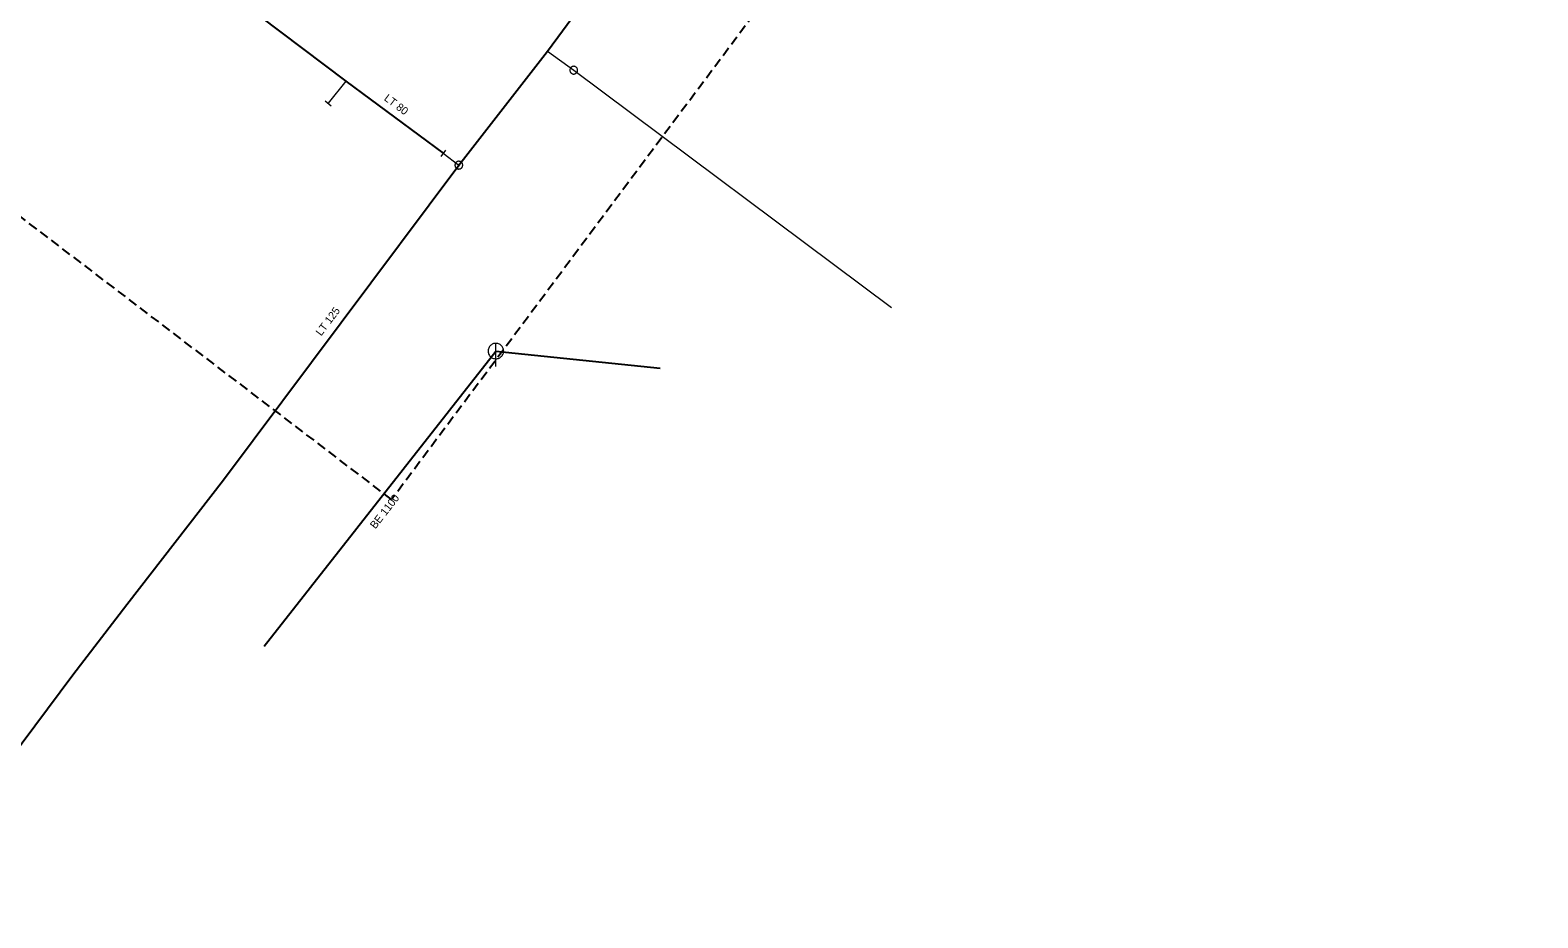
# Model space of a CAD drawing. Extents: x -791337 to -790755, y -988454 to -987923.
# Drawn here: x -790949.7 to -790755.1, y -988454.4 to -988339.8 of the extents above; entities that cross this region are included whole.
import ezdxf

# ---------------------------------------------------------------- set-up
doc = ezdxf.new("R2010")
doc.units = 0
doc.header["$LTSCALE"] = 0.4
doc.linetypes.add('MEDIUM_DASHED', pattern=[4.5, 3, -1.5])
for name, color, linetype, lineweight in [('1', 7, 'Continuous', 13), ('13', 7, 'Continuous', 13), ('14', 7, 'Continuous', 25), ('17', 7, 'Continuous', 25), ('22', 7, 'Continuous', 13), ('23', 7, 'Continuous', 13), ('34', 7, 'Continuous', 13), ('47', 7, 'Continuous', 13), ('63', 7, 'MEDIUM_DASHED', 25)]:
    doc.layers.add(name, color=color, linetype=linetype, lineweight=lineweight)

msp = doc.modelspace()

# ---------------------------------------------------------------- linework, layer by layer
at = {"layer": '13'}
for p, q in [((-790882.949, -988342.528), (-790879.522, -988345.001)), ((-790879.522, -988345.001), (-790838.539, -988375.636)), ((-790908.984, -988346.43), (-790911.247, -988349.284))]:
    msp.add_line(p, q, dxfattribs=at)
at = {"layer": '14', "lineweight": 13}
msp.add_line((-790896.409, -988355.739), (-790894.383, -988357.266), dxfattribs=at)
at = {"layer": '14'}
for p, q in [((-790919.509, -988419.376), (-790889.6, -988381.27)), ((-790889.6, -988381.27), (-790868.41, -988383.46))]:
    msp.add_line(p, q, dxfattribs=at)
at = {"layer": '17'}
for points in [[(-790942.565, -988321.078), (-790942.351, -988321.278), (-790925.727, -988333.706), (-790908.984, -988346.43), (-790896.409, -988355.739)], [(-790894.383, -988357.266), (-790882.949, -988342.528), (-790868.671, -988323.153)], [(-790967.649, -988454.445), (-790967.006, -988453.631), (-790944.219, -988423.054), (-790937.217, -988413.973), (-790924.743, -988397.888), (-790894.383, -988357.266)]]:
    msp.add_lwpolyline(points, dxfattribs=at)
at = {"layer": '22'}
msp.add_line((-790889.6, -988383.27), (-790889.599, -988380.27), dxfattribs=at)
msp.add_lwpolyline([(-790888.6, -988381.27), (-790888.605, -988381.161), (-790888.623, -988381.053), (-790888.653, -988380.947), (-790888.693, -988380.846), (-790888.745, -988380.749), (-790888.807, -988380.659), (-790888.879, -988380.576), (-790888.959, -988380.502), (-790889.047, -988380.436), (-790889.141, -988380.381), (-790889.241, -988380.336), (-790889.346, -988380.303), (-790889.453, -988380.281), (-790889.562, -988380.271), (-790889.672, -988380.273), (-790889.78, -988380.287), (-790889.887, -988380.312), (-790889.99, -988380.349), (-790890.088, -988380.398), (-790890.18, -988380.456), (-790890.266, -988380.525), (-790890.343, -988380.602), (-790890.412, -988380.688), (-790890.471, -988380.78), (-790890.519, -988380.878), (-790890.556, -988380.981), (-790890.582, -988381.088), (-790890.596, -988381.196), (-790890.599, -988381.306), (-790890.589, -988381.415), (-790890.568, -988381.522), (-790890.534, -988381.626), (-790890.49, -988381.726), (-790890.435, -988381.821), (-790890.369, -988381.909), (-790890.295, -988381.989), (-790890.212, -988382.061), (-790890.122, -988382.123), (-790890.026, -988382.175), (-790889.924, -988382.216), (-790889.819, -988382.246), (-790889.711, -988382.264), (-790889.601, -988382.27), (-790889.492, -988382.264), (-790889.384, -988382.246), (-790889.279, -988382.217), (-790889.177, -988382.176), (-790889.08, -988382.124), (-790888.99, -988382.062), (-790888.907, -988381.991), (-790888.832, -988381.911), (-790888.767, -988381.823), (-790888.711, -988381.729), (-790888.667, -988381.629), (-790888.633, -988381.525), (-790888.611, -988381.417), (-790888.601, -988381.308)], close=True, dxfattribs=at)
at = {"layer": '23'}
for points in [[(-790879.15, -988345.3), (-790879.121, -988345.256), (-790879.097, -988345.209), (-790879.079, -988345.161), (-790879.065, -988345.11), (-790879.057, -988345.059), (-790879.055, -988345.006), (-790879.057, -988344.954), (-790879.065, -988344.903), (-790879.078, -988344.852), (-790879.097, -988344.803), (-790879.12, -988344.756), (-790879.149, -988344.711), (-790879.182, -988344.671), (-790879.218, -988344.635), (-790879.258, -988344.601), (-790879.304, -988344.572), (-790879.349, -988344.549), (-790879.399, -988344.53), (-790879.448, -988344.516), (-790879.5, -988344.507), (-790879.553, -988344.505), (-790879.605, -988344.508), (-790879.658, -988344.516), (-790879.708, -988344.528), (-790879.756, -988344.547), (-790879.803, -988344.572), (-790879.846, -988344.6), (-790879.887, -988344.633), (-790879.924, -988344.67), (-790879.957, -988344.71), (-790879.986, -988344.754), (-790880.01, -988344.801), (-790880.029, -988344.85), (-790880.043, -988344.9), (-790880.05, -988344.951), (-790880.053, -988345.003), (-790880.051, -988345.056), (-790880.043, -988345.108), (-790880.029, -988345.159)], [(-790879.399, -988344.53), (-790879.448, -988344.516), (-790879.5, -988344.507), (-790879.553, -988344.505), (-790879.605, -988344.508), (-790879.658, -988344.516), (-790879.708, -988344.528), (-790879.756, -988344.547), (-790879.803, -988344.572), (-790879.846, -988344.6), (-790879.887, -988344.633), (-790879.924, -988344.67), (-790879.957, -988344.71), (-790879.986, -988344.754), (-790880.01, -988344.801), (-790880.029, -988344.85), (-790880.043, -988344.9), (-790880.05, -988344.951), (-790880.053, -988345.003), (-790880.051, -988345.056), (-790880.043, -988345.108), (-790880.029, -988345.159), (-790880.011, -988345.207), (-790879.987, -988345.254), (-790879.96, -988345.298), (-790879.925, -988345.339), (-790879.889, -988345.375), (-790879.849, -988345.408), (-790879.805, -988345.436), (-790879.758, -988345.461), (-790879.709, -988345.48), (-790879.659, -988345.493), (-790879.607, -988345.502), (-790879.555, -988345.505), (-790879.502, -988345.501), (-790879.451, -988345.494), (-790879.401, -988345.481), (-790879.351, -988345.462), (-790879.304, -988345.438), (-790879.261, -988345.41)], [(-790880.029, -988345.159), (-790880.011, -988345.207), (-790879.987, -988345.254), (-790879.96, -988345.298), (-790879.925, -988345.339), (-790879.889, -988345.375), (-790879.849, -988345.408), (-790879.805, -988345.436), (-790879.758, -988345.461), (-790879.709, -988345.48), (-790879.659, -988345.493), (-790879.607, -988345.502), (-790879.555, -988345.505), (-790879.502, -988345.501), (-790879.451, -988345.494), (-790879.401, -988345.481), (-790879.351, -988345.462), (-790879.304, -988345.438), (-790879.261, -988345.41), (-790879.22, -988345.376), (-790879.183, -988345.34), (-790879.15, -988345.3), (-790879.121, -988345.256), (-790879.097, -988345.209), (-790879.079, -988345.161), (-790879.065, -988345.11), (-790879.057, -988345.059), (-790879.055, -988345.006), (-790879.057, -988344.954), (-790879.065, -988344.903), (-790879.078, -988344.852), (-790879.097, -988344.803), (-790879.12, -988344.756), (-790879.149, -988344.711), (-790879.182, -988344.671), (-790879.218, -988344.635), (-790879.258, -988344.601), (-790879.304, -988344.572), (-790879.349, -988344.549), (-790879.399, -988344.53)], [(-790879.261, -988345.41), (-790879.22, -988345.376), (-790879.183, -988345.34), (-790879.15, -988345.3)]]:
    msp.add_lwpolyline(points, dxfattribs=at)
at = {"layer": '34'}
for p, q in [((-790911.639, -988348.973), (-790910.855, -988349.594)), ((-790896.11, -988355.337), (-790896.707, -988356.139))]:
    msp.add_line(p, q, dxfattribs=at)
at = {"layer": '47'}
for points in [[(-790894.045, -988357.635), (-790894.009, -988357.597), (-790893.976, -988357.556), (-790893.948, -988357.512), (-790893.924, -988357.466), (-790893.906, -988357.416), (-790893.893, -988357.365), (-790893.886, -988357.314), (-790893.883, -988357.262), (-790893.886, -988357.21), (-790893.894, -988357.158), (-790893.908, -988357.107), (-790893.928, -988357.059), (-790893.951, -988357.012), (-790893.981, -988356.969), (-790894.013, -988356.928), (-790894.051, -988356.892), (-790894.092, -988356.859), (-790894.136, -988356.831), (-790894.182, -988356.807), (-790894.232, -988356.789), (-790894.283, -988356.776), (-790894.335, -988356.768), (-790894.387, -988356.766), (-790894.439, -988356.768), (-790894.49, -988356.777), (-790894.541, -988356.791), (-790894.59, -988356.81), (-790894.636, -988356.834), (-790894.679, -988356.864), (-790894.72, -988356.896), (-790894.756, -988356.934), (-790894.789, -988356.975), (-790894.818, -988357.019), (-790894.841, -988357.065), (-790894.859, -988357.115), (-790894.873, -988357.165), (-790894.881, -988357.217), (-790894.883, -988357.269), (-790894.88, -988357.322), (-790894.871, -988357.373), (-790894.857, -988357.424), (-790894.838, -988357.472), (-790894.814, -988357.519), (-790894.784, -988357.562), (-790894.752, -988357.603), (-790894.714, -988357.639), (-790894.673, -988357.672), (-790894.63, -988357.7), (-790894.583, -988357.724), (-790894.533, -988357.742), (-790894.483, -988357.756), (-790894.432, -988357.763), (-790894.379, -988357.765), (-790894.327, -988357.762), (-790894.275, -988357.754), (-790894.224, -988357.74), (-790894.176, -988357.721), (-790894.129, -988357.697), (-790894.086, -988357.667)], [(-790894.327, -988357.326), (-790894.321, -988357.32), (-790894.316, -988357.313), (-790894.311, -988357.306), (-790894.308, -988357.299), (-790894.304, -988357.29), (-790894.303, -988357.282), (-790894.301, -988357.273), (-790894.3, -988357.265), (-790894.301, -988357.256), (-790894.302, -988357.248), (-790894.305, -988357.239), (-790894.308, -988357.231), (-790894.312, -988357.224), (-790894.316, -988357.217), (-790894.322, -988357.21), (-790894.328, -988357.204), (-790894.335, -988357.199), (-790894.342, -988357.194), (-790894.349, -988357.191), (-790894.358, -988357.187), (-790894.366, -988357.186), (-790894.375, -988357.184), (-790894.383, -988357.183), (-790894.392, -988357.184), (-790894.4, -988357.185), (-790894.409, -988357.188), (-790894.417, -988357.191), (-790894.424, -988357.195), (-790894.431, -988357.199), (-790894.438, -988357.205), (-790894.444, -988357.211), (-790894.449, -988357.218), (-790894.454, -988357.225), (-790894.457, -988357.232), (-790894.461, -988357.241), (-790894.463, -988357.248), (-790894.464, -988357.258), (-790894.465, -988357.266), (-790894.464, -988357.275), (-790894.463, -988357.283), (-790894.46, -988357.292), (-790894.457, -988357.3), (-790894.453, -988357.307), (-790894.449, -988357.314), (-790894.443, -988357.321), (-790894.437, -988357.327), (-790894.43, -988357.332), (-790894.423, -988357.337), (-790894.416, -988357.34), (-790894.407, -988357.344), (-790894.4, -988357.346), (-790894.39, -988357.347), (-790894.382, -988357.348), (-790894.373, -988357.347), (-790894.365, -988357.346), (-790894.356, -988357.343), (-790894.348, -988357.34), (-790894.341, -988357.336), (-790894.334, -988357.332)]]:
    msp.add_lwpolyline(points, close=True, dxfattribs=at)
at = {"layer": '63'}
msp.add_lwpolyline([(-791231.02, -987923.132), (-790755.118, -988202.253), (-790755.118, -988202.253), (-790903.053, -988400.429), (-790903.053, -988400.429), (-791331.504, -988073.857), (-791331.504, -988073.857)], close=True, dxfattribs=at)

# ---------------------------------------------------------------- texts
at = {"layer": '1'}
for s, rotation, p in [('LT 80 ', 323, (-790904.119, -988348.805)), ('LT 125', 53, (-790912.148, -988379.39)), ('BE 1100 ', 52, (-790905.153, -988404.301))]:
    msp.add_text(s, height=1, rotation=rotation, dxfattribs=at).set_placement(p)

doc.saveas('drawing.dxf')
